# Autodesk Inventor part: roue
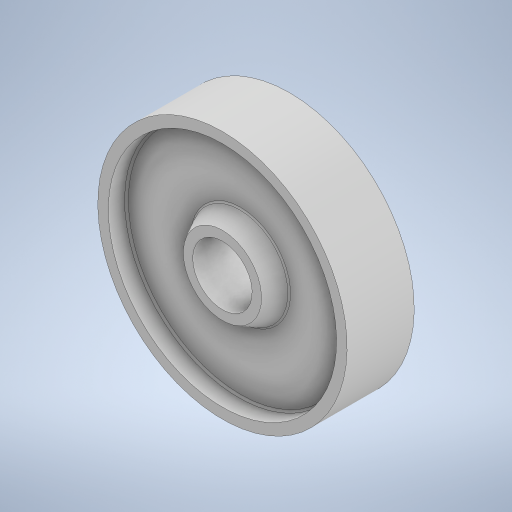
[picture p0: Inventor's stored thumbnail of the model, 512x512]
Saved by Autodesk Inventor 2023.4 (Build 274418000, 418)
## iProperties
Created: 2025-03
Part Number: roue
Material: Générique
Document SubType Name: Modeling
Designer: bruno
Density: 1 g/cm^3
Appearance: Par défaut
Author: bruno
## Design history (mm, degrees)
sketch "Esquisse1"
  geometry: L1 (0, 0)-(0, -21.494); L2 (40.822, 7.6)-(31, 7.6); L3 (31, 7.6)-(31, -27.4); L4 (130, 7.6)-(119.051, 7.6); L5 (119.051, 7.6)-(119.051, -9.385); L6 (130, -27.4)-(130, 7.6); L7 (31, -27.4)-(130, -27.4); L8 (40.822, 7.6)-(50.311, -10.321); L9 (52.079, -11.385)-(117.051, -11.385); A1 r 2 centre (117.051, -9.385) between (117.051, -11.385) and (119.051, -9.385); A2 r 2 centre (52.079, -9.385) between (50.311, -10.321) and (52.079, -11.385); 1 further point
  constraints: 18 end point, 4 point on circle, 4 tangent, 3 perpendicular, 2 centre point, 2 horizontal, 2 parallel, 1 equal radius, 1 midpoint, 1 vertical
  dimensions: "d0" = 2 radius of A1 (derived); "d1" = 130 distance between parallel lines of L1 L6; "d2" = 31 distance between parallel lines of L1 L3; "d4" = 35 distance from line of L7 point (124.526, 7.6)
revolve "Révolution1" sketch "Esquisse1" stored, may be unused: angle "d3" = 90 deg
mirror "Symétrie1"
node "Solide1"
